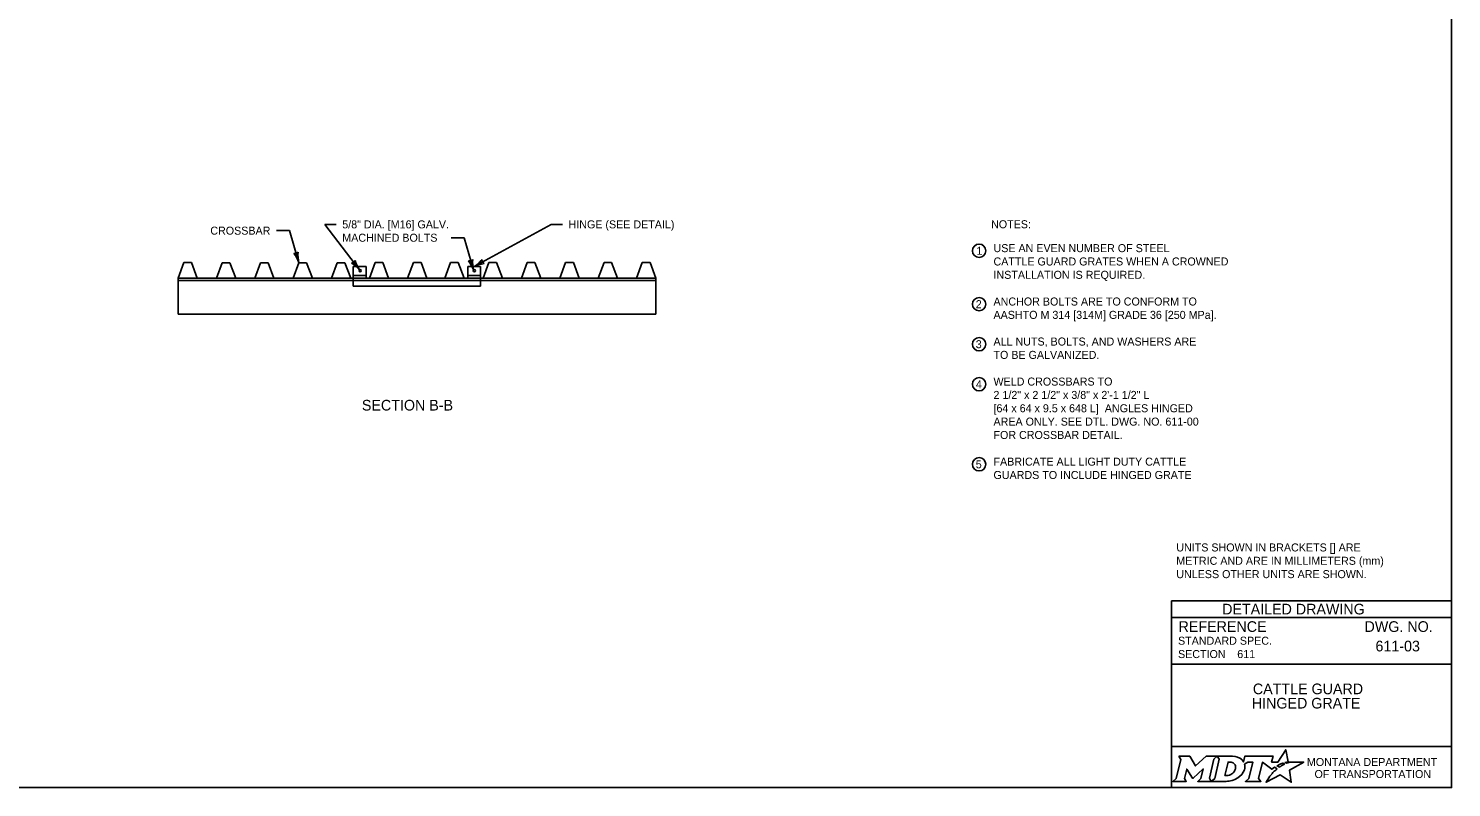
# Model space of a CAD drawing. Extents: x 49991.4 to 50021, y 49987.6 to 50011.4.
# Drawn here: x 50006.08 to 50016.75, y 49987.8 to 49993.49 of the extents above; entities that cross this region are included whole.
import ezdxf

# ---------------------------------------------------------------- set-up
doc = ezdxf.new("R2010")
doc.units = 0
for name, color, linetype in [('Default', 7, 'Continuous'), ('Level 1', 7, 'Continuous'), ('Level 2', 7, 'Continuous'), ('Level 3', 7, 'Continuous'), ('Level 4', 7, 'Continuous'), ('Level 5', 7, 'Continuous')]:
    doc.layers.add(name, color=color, linetype=linetype)

msp = doc.modelspace()

# ---------------------------------------------------------------- linework, layer by layer
at = {"layer": 'Default'}
for points in [[(50015.513, 49987.981), (50015.502, 49987.987), (50015.514, 49987.99), (50015.526, 49987.991), (50015.508, 49988.082), (50015.449, 49987.99), (50015.401, 49987.99), (50015.412, 49988.034), (50015.202, 49988.034), (50015.192, 49987.991), (50015.186, 49988)], [(50014.706, 49988.034), (50014.72, 49988.01), (50014.686, 49987.867), (50014.66, 49987.845), (50014.762, 49987.845), (50014.749, 49987.867), (50014.765, 49987.937), (50014.809, 49987.868), (50014.814, 49987.868), (50014.889, 49987.938), (50014.872, 49987.867), (50014.848, 49987.845), (50014.949, 49987.845), (50014.936, 49987.868), (50014.969, 49988.011)], [(50014.969, 49988.011), (50014.994, 49988.034), (50014.912, 49988.034), (50014.832, 49987.961), (50014.788, 49988.034), (50014.706, 49988.034)], [(50015.108, 49988.034), (50014.994, 49988.034), (50015.009, 49988.011), (50014.975, 49987.867), (50014.949, 49987.845), (50015.06, 49987.845)], [(50015.132, 49987.947), (50015.13, 49987.939), (50015.127, 49987.93), (50015.123, 49987.922), (50015.118, 49987.914), (50015.111, 49987.907), (50015.103, 49987.901), (50015.095, 49987.896), (50015.086, 49987.892), (50015.077, 49987.89), (50015.067, 49987.889), (50015.052, 49987.889), (50015.075, 49987.989), (50015.091, 49987.989), (50015.099, 49987.988), (50015.106, 49987.986), (50015.113, 49987.983), (50015.119, 49987.979), (50015.124, 49987.974), (50015.128, 49987.968), (50015.13, 49987.962), (50015.132, 49987.955), (50015.132, 49987.952), (50015.132, 49987.947)], [(50015.199, 49987.975), (50015.224, 49987.988), (50015.261, 49987.988), (50015.232, 49987.867), (50015.205, 49987.845), (50015.321, 49987.845), (50015.304, 49987.867), (50015.332, 49987.988), (50015.403, 49987.936), (50015.424, 49987.951), (50015.444, 49987.94)], [(50015.388, 49987.884), (50015.373, 49987.86), (50015.368, 49987.852), (50015.362, 49987.844), (50015.36, 49987.839), (50015.465, 49987.893), (50015.549, 49987.838), (50015.536, 49987.93), (50015.643, 49987.989), (50015.594, 49987.989), (50015.564, 49987.99), (50015.543, 49987.99), (50015.536, 49987.989), (50015.531, 49987.987), (50015.523, 49987.985), (50015.513, 49987.981)], [(50015.462, 49987.954), (50015.46, 49987.952), (50015.442, 49987.961), (50015.452, 49987.967), (50015.456, 49987.969), (50015.465, 49987.973), (50015.47, 49987.976), (50015.478, 49987.979), (50015.485, 49987.982), (50015.497, 49987.974), (50015.493, 49987.972), (50015.489, 49987.97), (50015.484, 49987.967), (50015.479, 49987.965), (50015.478, 49987.963), (50015.475, 49987.962), (50015.472, 49987.96), (50015.47, 49987.959), (50015.467, 49987.957), (50015.465, 49987.955), (50015.462, 49987.954)], [(50015.106, 49987.852), (50015.114, 49987.855), (50015.127, 49987.86), (50015.148, 49987.871)], [(50015.402, 49987.9), (50015.402, 49987.9)]]:
    msp.add_lwpolyline(points, dxfattribs=at)
for centre, radius, start, end in [((50015.131, 49987.955), 0.0709, 339.5329, 15.8582), ((50015.087, 49987.973), 0.118, 300.9103, 339.1383)]:
    msp.add_arc(centre, radius, start, end, dxfattribs=at)
for centre, major_axis, ratio, start_param, end_param in [((50015.106, 49987.986), (0.0834, -0.0037), 0.568097, 0.61298, 1.570796), ((50015.161, 49987.994), (0.0361, -0.0295), 0.469099, 1.225588, 1.570796), ((50015.06, 49987.993), (0, 0.148), 0.987302, 3.139398, 3.456847), ((50015.395, 49987.892), (-0.00694, -0.00806), 0.008222, 0, 3.137361), ((50015.412, 49987.911), (-0.0098, -0.0102), 0.016458, 3.141593, 6.279097), ((50015.433, 49987.93), (-0.0112, -0.0097), 0.021651, 3.157348, 6.283185)]:
    msp.add_ellipse(centre, major_axis=major_axis, ratio=ratio, start_param=start_param, end_param=end_param, dxfattribs=at)
at = {"layer": 'Level 1'}
for p, q in [((50007.248, 49991.733), (50007.205, 49991.617)), ((50007.248, 49991.733), (50007.306, 49991.733)), ((50007.306, 49991.733), (50007.349, 49991.617)), ((50007.536, 49991.732), (50007.493, 49991.617)), ((50007.536, 49991.732), (50007.594, 49991.732)), ((50007.594, 49991.732), (50007.637, 49991.617)), ((50007.824, 49991.732), (50007.78, 49991.617)), ((50007.824, 49991.732), (50007.881, 49991.732)), ((50007.881, 49991.732), (50007.924, 49991.617)), ((50008.111, 49991.732), (50008.068, 49991.617)), ((50008.111, 49991.732), (50008.169, 49991.732)), ((50008.169, 49991.732), (50008.212, 49991.617)), ((50008.398, 49991.732), (50008.355, 49991.617)), ((50008.398, 49991.732), (50008.456, 49991.732)), ((50008.456, 49991.732), (50008.499, 49991.617)), ((50008.615, 49991.704), (50008.518, 49991.704)), ((50008.518, 49991.617), (50008.518, 49991.704)), ((50008.615, 49991.617), (50008.615, 49991.704)), ((50008.682, 49991.733), (50008.639, 49991.617)), ((50008.682, 49991.733), (50008.74, 49991.733)), ((50008.74, 49991.733), (50008.783, 49991.617)), ((50008.969, 49991.733), (50008.926, 49991.617)), ((50008.969, 49991.733), (50009.027, 49991.733)), ((50009.027, 49991.733), (50009.07, 49991.617)), ((50009.248, 49991.733), (50009.204, 49991.617)), ((50009.248, 49991.733), (50009.305, 49991.733)), ((50009.305, 49991.733), (50009.349, 49991.617)), ((50009.376, 49991.617), (50009.376, 49991.704)), ((50009.473, 49991.704), (50009.376, 49991.704)), ((50009.473, 49991.617), (50009.473, 49991.704)), ((50009.535, 49991.733), (50009.492, 49991.617)), ((50009.535, 49991.733), (50009.593, 49991.733)), ((50009.593, 49991.733), (50009.636, 49991.617)), ((50009.823, 49991.733), (50009.779, 49991.617)), ((50009.823, 49991.733), (50009.88, 49991.733)), ((50009.88, 49991.733), (50009.924, 49991.617)), ((50010.11, 49991.733), (50010.067, 49991.617)), ((50010.11, 49991.733), (50010.168, 49991.733)), ((50010.168, 49991.733), (50010.211, 49991.617)), ((50010.398, 49991.733), (50010.354, 49991.617)), ((50010.398, 49991.733), (50010.455, 49991.733)), ((50010.455, 49991.733), (50010.499, 49991.617)), ((50010.685, 49991.734), (50010.641, 49991.617)), ((50010.685, 49991.734), (50010.743, 49991.734)), ((50010.743, 49991.734), (50010.786, 49991.617)), ((50007.205, 49991.617), (50010.786, 49991.617)), ((50007.205, 49991.617), (50007.205, 49991.345)), ((50007.205, 49991.598), (50010.786, 49991.598)), ((50008.615, 49991.635), (50008.518, 49991.635)), ((50009.376, 49991.635), (50009.473, 49991.635)), ((50010.786, 49991.617), (50010.786, 49991.345)), ((50007.205, 49991.345), (50010.786, 49991.345))]:
    msp.add_line(p, q, dxfattribs=at)
msp.add_lwpolyline([(49999.384, 49998.999), (50016.75, 49998.999), (50016.75, 49987.799), (49999.384, 49987.799)], close=True, dxfattribs=at)
for centre in [(50008.57, 49991.672), (50009.426, 49991.672)]:
    msp.add_circle(centre, 0.00832, dxfattribs=at)
at = {"layer": 'Level 2'}
for centre in [(50013.209, 49991.821), (50013.209, 49991.421), (50013.209, 49991.121), (50013.209, 49990.821), (50013.209, 49990.221)]:
    msp.add_circle(centre, 0.05, dxfattribs=at)
at = {"layer": 'Level 3'}
for p, q in [((50008.306, 49992.019), (50008.564, 49991.678)), ((50008.391, 49992.019), (50008.306, 49992.019)), ((50009.424, 49991.704), (50010.002, 49992.019)), ((50010.087, 49992.019), (50010.002, 49992.019)), ((50008.04, 49991.972), (50007.944, 49991.972)), ((50009.349, 49991.918), (50009.253, 49991.918))]:
    msp.add_line(p, q, dxfattribs=at)
for points in [[(50008.111, 49991.732), (50008.04, 49991.972)], [(50009.42, 49991.678), (50009.349, 49991.918)]]:
    msp.add_lwpolyline(points, dxfattribs=at)
for centre, radius, start, end in [((50008.074, 49991.855), 0.0548, 269.0982, 304.8206), ((50007.892, 49991.654), 0.233, 19.7867, 39.0365), ((50008.326, 49991.788), 0.222, 174.4154, 194.5989), ((50008.487, 49991.78), 0.0548, 289.2949, 325.0172), ((50008.386, 49991.528), 0.233, 39.9834, 59.2332), ((50008.747, 49991.805), 0.222, 194.6121, 214.7956), ((50009.382, 49991.801), 0.0548, 269.0982, 304.8206), ((50009.2, 49991.599), 0.233, 19.7867, 39.0365), ((50009.635, 49991.734), 0.222, 174.4154, 194.5989), ((50009.303, 49991.902), 0.233, 301.4653, 320.7151), ((50009.523, 49991.504), 0.222, 96.094, 116.2775), ((50009.537, 49991.765), 0.0548, 190.7768, 226.4992)]:
    msp.add_arc(centre, radius, start, end, dxfattribs=at)
at = {"layer": 'Level 4'}
for p, q in [((50008.518, 49991.617), (50008.517, 49991.555)), ((50009.471, 49991.555), (50009.473, 49991.617)), ((50008.517, 49991.555), (50009.471, 49991.555))]:
    msp.add_line(p, q, dxfattribs=at)
at = {"layer": 'Level 5'}
for p, q in [((50016.75, 49989.199), (50014.65, 49989.199)), ((50014.65, 49989.199), (50014.65, 49987.799)), ((50016.75, 49989.074), (50014.65, 49989.074)), ((50016.386, 49988.859), (50016.386, 49988.859)), ((50016.75, 49988.724), (50014.65, 49988.724)), ((50015.144, 49988.799), (50015.144, 49988.799)), ((50015.7, 49988.475), (50015.7, 49988.475)), ((50016.75, 49988.106), (50014.65, 49988.106))]:
    msp.add_line(p, q, dxfattribs=at)

# ---------------------------------------------------------------- texts
at = {"layer": 'Default'}
for s, p in [('MONTANA DEPARTMENT', (50015.666, 49987.96)), ('OF TRANSPORTATION', (50015.723, 49987.87))]:
    msp.add_text(s, height=0.06, dxfattribs=at).set_placement(p)
at = {"layer": 'Level 2'}
for s, height, p in [('CROSSBAR', 0.06, (50007.447, 49991.942)), ('5/8" DIA. [M16] GALV.', 0.06, (50008.436, 49991.989)), ('HINGE (SEE DETAIL)', 0.06, (50010.132, 49991.989)), ('NOTES:', 0.06, (50013.299, 49991.99)), ('MACHINED BOLTS', 0.06, (50008.436, 49991.889)), ('1', 0.06, (50013.189, 49991.791)), ('USE AN EVEN NUMBER OF STEEL', 0.06, (50013.317, 49991.811)), ('CATTLE GUARD GRATES WHEN A CROWNED', 0.06, (50013.317, 49991.711)), ('INSTALLATION IS REQUIRED. ', 0.06, (50013.317, 49991.611)), ('ANCHOR BOLTS ARE TO CONFORM TO ', 0.06, (50013.317, 49991.411)), ('2', 0.06, (50013.184, 49991.391)), ('AASHTO M 314 [314M] GRADE 36 [250 MPa].', 0.06, (50013.317, 49991.311)), ('3', 0.06, (50013.184, 49991.091)), ('ALL NUTS, BOLTS, AND WASHERS ARE', 0.06, (50013.317, 49991.111)), ('TO BE GALVANIZED.', 0.06, (50013.317, 49991.011)), ('4', 0.06, (50013.185, 49990.791)), ('WELD CROSSBARS TO ', 0.06, (50013.317, 49990.811)), ('2 1/2" x 2 1/2" x 3/8" x 2\'-1 1/2" L', 0.06, (50013.317, 49990.711)), ('SECTION B-B', 0.08, (50008.583, 49990.624)), ('[64 x 64 x 9.5 x 648 L]  ANGLES HINGED', 0.06, (50013.317, 49990.611)), ('AREA ONLY. SEE DTL. DWG. NO. 611-00 ', 0.06, (50013.317, 49990.511)), ('FOR CROSSBAR DETAIL.', 0.06, (50013.317, 49990.411)), ('5', 0.06, (50013.184, 49990.191)), ('FABRICATE ALL LIGHT DUTY CATTLE ', 0.06, (50013.317, 49990.211)), ('GUARDS TO INCLUDE HINGED GRATE', 0.06, (50013.317, 49990.111)), ('UNITS SHOWN IN BRACKETS [] ARE ', 0.06, (50014.687, 49989.568)), ('METRIC AND ARE IN MILLIMETERS (mm) ', 0.06, (50014.687, 49989.468)), ('UNLESS OTHER UNITS ARE SHOWN.', 0.06, (50014.687, 49989.368)), ('611', 0.06, (50015.144, 49988.769)), ('611-03', 0.08, (50016.18, 49988.819)), ('CATTLE GUARD', 0.08, (50015.261, 49988.498)), ('HINGED GRATE', 0.08, (50015.253, 49988.391))]:
    msp.add_text(s, height=height, dxfattribs=at).set_placement(p)
at = {"layer": 'Level 5'}
for s, height, p in [('DETAILED DRAWING', 0.0799, (50015.031, 49989.096)), ('REFERENCE', 0.08, (50014.704, 49988.965)), ('DWG. NO.', 0.08, (50016.098, 49988.965)), ('STANDARD SPEC.', 0.06, (50014.7, 49988.869)), ('SECTION', 0.06, (50014.7, 49988.769))]:
    msp.add_text(s, height=height, dxfattribs=at).set_placement(p)

doc.saveas('drawing.dxf')
